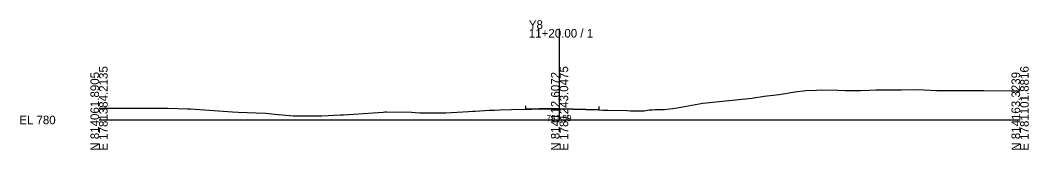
# Model space of a CAD drawing. Extents: x -26 to 303, y -10 to 5036.
# Drawn here: x -25.7 to 302.8, y 1490.3 to 1532.4 of the extents above; entities that cross this region are included whole.
import ezdxf

# ---------------------------------------------------------------- set-up
doc = ezdxf.new("R2010")
doc.units = 0
for name, color, linetype in [('Exist Cross Section Cell', 7, 'Continuous'), ('Exist XS Center Line Elevation Label', 7, 'Continuous'), ('Exist XS Ground Line', 7, 'Continuous'), ('Prop XS EOT Tick Mark', 7, 'Continuous'), ('Prop XS Finish Grade Pavement', 7, 'Continuous')]:
    doc.layers.add(name, color=color, linetype=linetype)

msp = doc.modelspace()

# ---------------------------------------------------------------- linework, layer by layer
at = {"layer": 'Exist Cross Section Cell'}
for p, q in [((150, 1500), (150, 1529.58)), ((0, 1500), (150, 1500)), ((150, 1500), (300, 1500))]:
    msp.add_line(p, q, dxfattribs=at)
at = {"layer": 'Exist XS Ground Line'}
for p, q in [((216.62, 1507.7), (221.52, 1508.33)), ((221.52, 1508.33), (226.66, 1509.12)), ((226.66, 1509.12), (230.23, 1509.55)), ((230.23, 1509.55), (233.68, 1509.72)), ((233.68, 1509.72), (235.26, 1509.75)), ((235.26, 1509.75), (240.66, 1509.67)), ((240.66, 1509.67), (242.98, 1509.6)), ((242.98, 1509.6), (248.03, 1509.62)), ((248.03, 1509.62), (250.79, 1509.67)), ((250.79, 1509.67), (252.99, 1509.77)), ((252.99, 1509.77), (261.37, 1509.81)), ((261.37, 1509.81), (266.59, 1509.86)), ((266.59, 1509.86), (272.8, 1509.61)), ((272.8, 1509.61), (273.88, 1509.6)), ((273.88, 1509.6), (274.68, 1509.61)), ((274.68, 1509.61), (279.55, 1509.61)), ((279.55, 1509.61), (282.72, 1509.62)), ((282.72, 1509.62), (288.15, 1509.61)), ((288.15, 1509.61), (297.09, 1509.49)), ((297.09, 1509.49), (300, 1509.48)), ((189.48, 1504.11), (196.7, 1505.41)), ((196.7, 1505.41), (212.66, 1507.13)), ((212.66, 1507.13), (216.62, 1507.7)), ((0, 1503.85), (3.06, 1503.86)), ((3.06, 1503.86), (10.15, 1503.82)), ((10.15, 1503.82), (16.64, 1503.78)), ((16.64, 1503.78), (22.45, 1503.78)), ((22.45, 1503.78), (28.8, 1503.63)), ((28.8, 1503.63), (29.25, 1503.58)), ((29.25, 1503.58), (29.74, 1503.57)), ((29.74, 1503.57), (43.45, 1502.69)), ((43.45, 1502.69), (45.35, 1502.58)), ((45.35, 1502.58), (51.22, 1502.29)), ((51.22, 1502.29), (54.3, 1502.17)), ((54.3, 1502.17), (57.29, 1501.88)), ((57.29, 1501.88), (63.27, 1501.37)), ((72.56, 1501.37), (78.64, 1501.62)), ((78.64, 1501.62), (79.6, 1501.7)), ((79.6, 1501.7), (82.86, 1501.9)), ((82.86, 1501.9), (92.49, 1502.56)), ((92.49, 1502.56), (93.07, 1502.59)), ((93.07, 1502.59), (93.59, 1502.6)), ((93.59, 1502.6), (101.79, 1502.48)), ((101.79, 1502.48), (102.97, 1502.41)), ((102.97, 1502.41), (104.53, 1502.29)), ((104.53, 1502.29), (111.27, 1502.3)), ((111.27, 1502.3), (112.12, 1502.3)), ((112.12, 1502.3), (112.91, 1502.35)), ((112.91, 1502.35), (120.37, 1502.77)), ((120.37, 1502.77), (121.78, 1502.85)), ((121.78, 1502.85), (122.48, 1502.9)), ((122.48, 1502.9), (127.07, 1503.13)), ((127.07, 1503.13), (127.47, 1503.16)), ((127.47, 1503.16), (128.69, 1503.22)), ((128.69, 1503.22), (130.55, 1503.34)), ((130.55, 1503.34), (134.35, 1503.4)), ((134.35, 1503.4), (147.5, 1503.66)), ((147.5, 1503.66), (150, 1503.59)), ((150, 1503.59), (162.91, 1503.24)), ((162.91, 1503.24), (164.09, 1503.21)), ((164.09, 1503.21), (164.58, 1503.18)), ((164.58, 1503.18), (165.72, 1503.15)), ((165.72, 1503.15), (172.05, 1503.04)), ((172.05, 1503.04), (173.15, 1503)), ((173.15, 1503), (174.2, 1502.97)), ((174.2, 1502.97), (177.56, 1502.95)), ((177.56, 1502.95), (179.21, 1503.25)), ((179.21, 1503.25), (180.29, 1503.33)), ((180.29, 1503.33), (181.15, 1503.38)), ((181.15, 1503.38), (182.43, 1503.43)), ((182.43, 1503.43), (184.18, 1503.43)), ((184.18, 1503.43), (184.88, 1503.56)), ((184.88, 1503.56), (186.89, 1503.73)), ((186.89, 1503.73), (188.9, 1504.07)), ((188.9, 1504.07), (189.48, 1504.11)), ((63.27, 1501.37), (68.57, 1501.37)), ((68.57, 1501.37), (70.91, 1501.32)), ((70.91, 1501.32), (72.56, 1501.37))]:
    msp.add_line(p, q, dxfattribs=at)
at = {"layer": 'Prop XS EOT Tick Mark'}
for p, q in [((139, 1503.62), (139, 1504.62)), ((162.91, 1503.37), (162.91, 1504.37))]:
    msp.add_line(p, q, dxfattribs=at)
at = {"layer": 'Prop XS Finish Grade Pavement'}
for p, q in [((139, 1503.62), (147.5, 1503.79)), ((147.5, 1503.79), (150, 1503.72)), ((150, 1503.72), (162.91, 1503.37))]:
    msp.add_line(p, q, dxfattribs=at)

# ---------------------------------------------------------------- texts
at = {"layer": 'Exist Cross Section Cell'}
for s, p in [('Y8', (140, 1529.58)), ('11+20.00 / 1', (140, 1526.78)), ('EL 780', (-26, 1498.6))]:
    msp.add_text(s, height=2.8, dxfattribs=at).set_placement(p)
for s, p in [('N 814061.8905', (0, 1490)), ('E 1781384.2135', (2.8, 1490)), ('N 814112.6072', (150, 1490)), ('E 1781243.0475', (152.8, 1490)), ('N 814163.3239', (300, 1490)), ('E 1781101.8816', (302.8, 1490))]:
    msp.add_text(s, height=2.8, rotation=90, dxfattribs=at).set_placement(p)
at = {"layer": 'Exist XS Center Line Elevation Label'}
msp.add_text('783.59', height=2, dxfattribs=at).set_placement((145.73, 1499.59))

doc.saveas('drawing.dxf')
